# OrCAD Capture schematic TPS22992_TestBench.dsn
size A; title: 5.5-V, 6-A, 10-mO load switch with adjustable rise time and adjustable quick output discharge; note: Datasheet: SLVSFT0                   EVM: SLVUC70
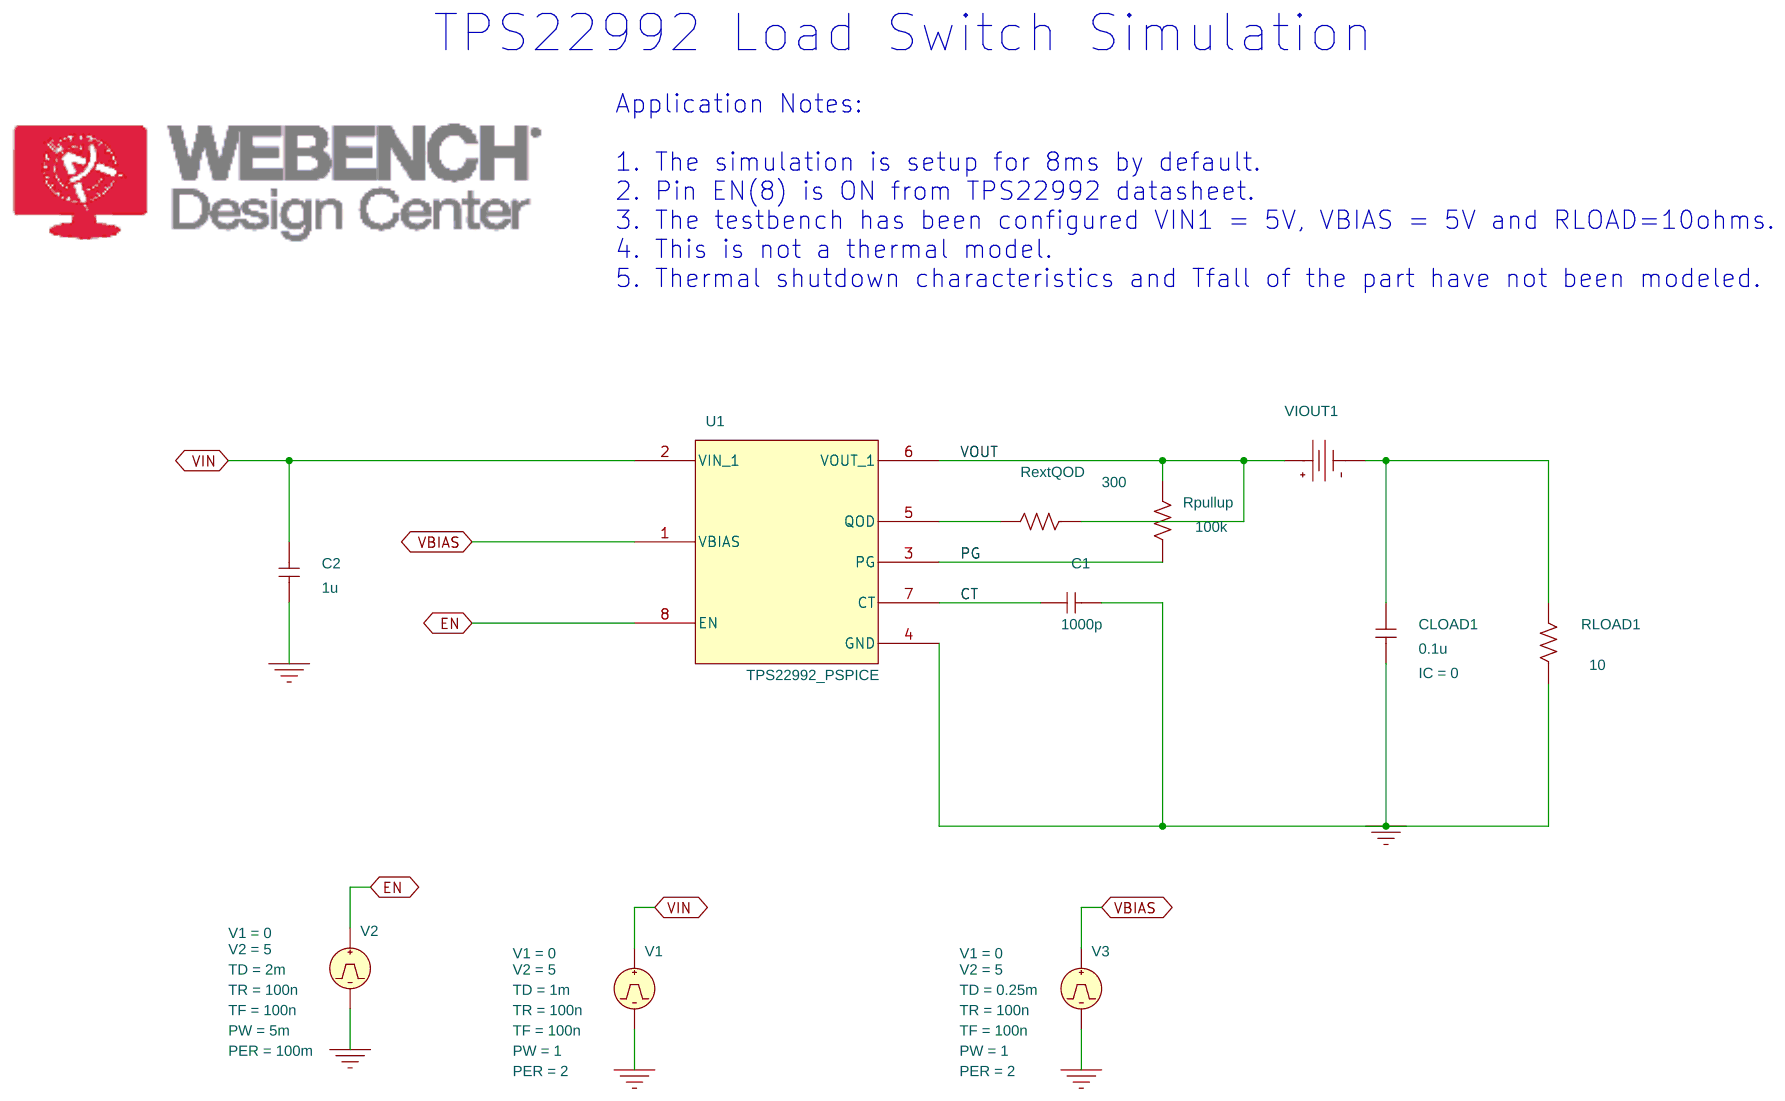
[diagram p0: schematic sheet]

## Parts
C1  1000p  [RAD/CK05]
C2  1u  [RAD/CK05]
CLOAD1  0.1u  [RAD/CK05]
RextQOD  300  [AX/RC05]
RLOAD1  10  [AX/RC05]
Rpullup  100k  [AX/RC05]
U1  TPS22992_PSPICE
V1  VPULSE
V2  VPULSE
V3  VPULSE
VIOUT1  VDC

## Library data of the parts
C1 C2 = C
CLOAD1 = C: IC: 0
RextQOD RLOAD1 Rpullup = R
U1 = TPS22992_PSPICE
V1 = VPULSE: PER: 2; PW: 1; TD: 1m; TF: 100n; TR: 100n; V1: 0; V2: 5
V2 = VPULSE: PER: 100m; PW: 5m; TD: 2m; TF: 100n; TR: 100n; V1: 0; V2: 5
V3 = VPULSE: PER: 2; PW: 1; TD: 0.25m; TF: 100n; TR: 100n; V1: 0; V2: 5
VIOUT1 = VDC

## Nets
VIN: C2.2 U1.2(VIN_1) V1.1(+)
0: C1.2 C2.1 CLOAD1.2 RLOAD1.1 U1.4(GND) V1.2(-) V2.2(-) V3.2(-)
CT: C1.1 U1.7(CT)
EN: U1.8(EN) V2.1(+)
PG: Rpullup.1 U1.3(PG)
VBIAS: U1.1(VBIAS) V3.1(+)
VOUT: RextQOD.1 Rpullup.2 U1.6(VOUT_1) VIOUT1.0(+)
N54246: CLOAD1.1 RLOAD1.2 VIOUT1.1(-)
N54360: RextQOD.2 U1.5(QOD)

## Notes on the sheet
- TPS22992 Load Switch Simulation
- Application Notes:
  1. The simulation is setup for 8ms by default.
  2. Pin EN(8) is ON from TPS22992 datasheet.
  3. The testbench has been configured VIN1 = 5V, VBIAS = 5V and RLOAD=10ohms.
  4. This is not a thermal model.
  5. Thermal shutdown characteristics and Tfall of the part have not been modeled.
